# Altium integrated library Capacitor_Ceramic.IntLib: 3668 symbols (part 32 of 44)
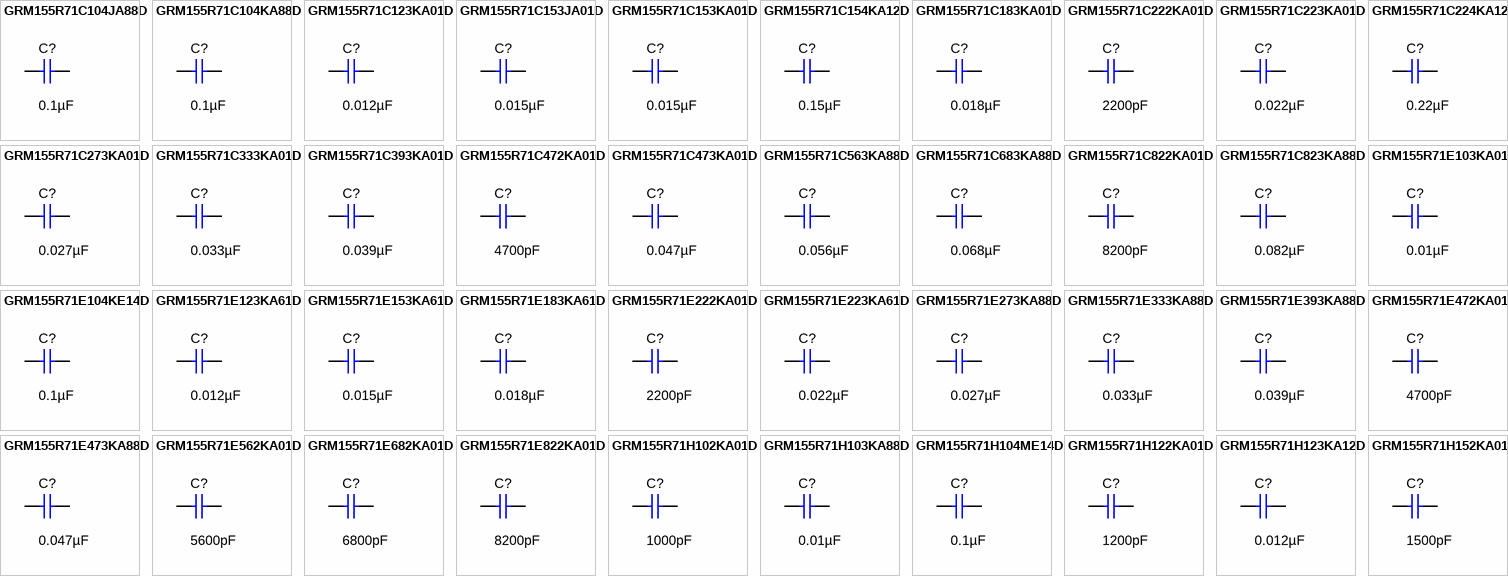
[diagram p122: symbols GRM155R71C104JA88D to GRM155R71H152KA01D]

## GRM155R71H123KA12D
designator C?  ValueDisplayed: 0.012µF  (hidden comment: GRM155R71H123KA12D)
CAP, CERM, 0.012 µF, 50 V,+/- 10%, X7R, 0402; Manufacturer: MuRata; Polarized: N; CompType: Capacitor; Value: 0.012uF; U/M: EA; Cap_F: 0.000000012; Tolerance_%: 10; VDC_V: 50; Value2: 50V; TaMin_C: -55; TaMax_C: 125; Cap_Case: 0402; SizeArea_mm2: 0.5; SizeAreaWB_mm2: 3; SizeX_mm: 1; SizeZ_mm: 0.6; AEC Category: Q200
signal-integrity model Cap
simulation model Cap
footprint 0402
footprint 0402M
footprint 0402L
footprint 0402S
pins: 1, 2

## GRM155R71H152KA01D
designator C?  ValueDisplayed: 1500pF  (hidden comment: GRM155R71H152KA01D)
CAP, CERM, 1500 pF, 50 V,+/- 10%, X7R, 0402; Manufacturer: MuRata; Polarized: N; CompType: Capacitor; Value: 1500pF; U/M: EA; Cap_F: 0.0000000015; Tolerance_%: 10; VDC_V: 50; Value2: 50V; TaMin_C: -55; TaMax_C: 125; Cap_Case: 0402; SizeArea_mm2: 0.5; SizeAreaWB_mm2: 3; SizeX_mm: 1; SizeZ_mm: 0.6; AEC Category: Q200
signal-integrity model Cap
simulation model Cap
footprint 0402
footprint 0402M
footprint 0402L
footprint 0402S
pins: 1, 2

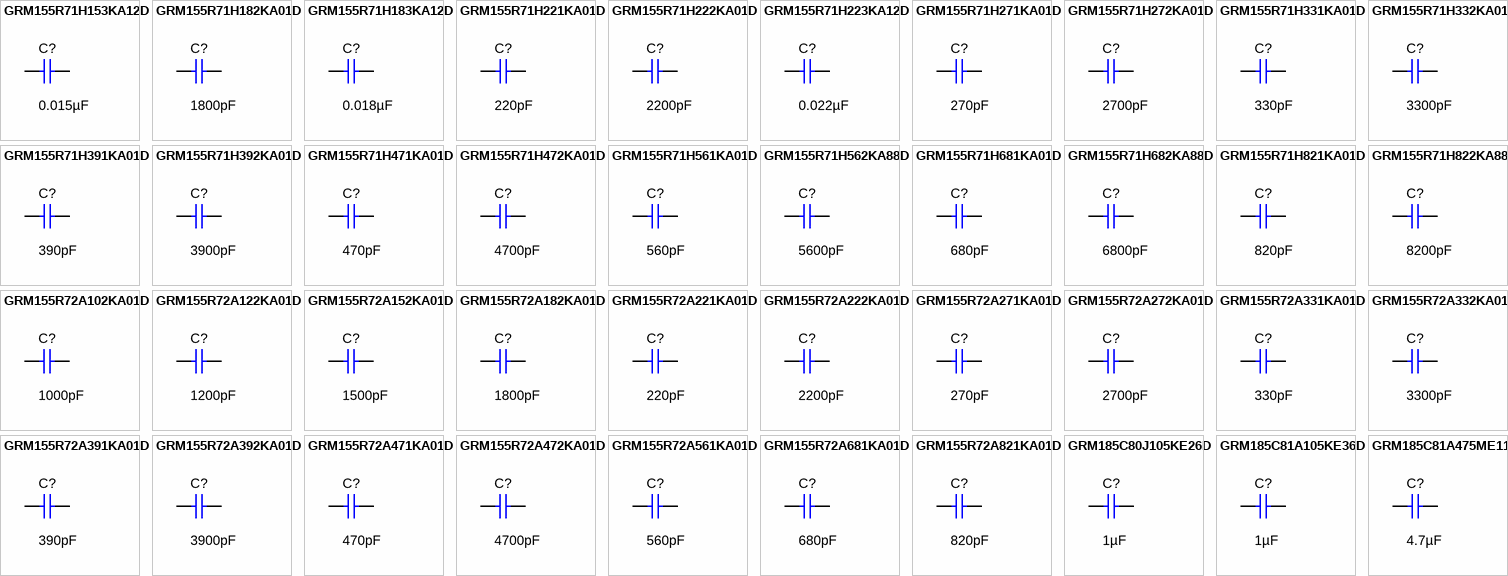
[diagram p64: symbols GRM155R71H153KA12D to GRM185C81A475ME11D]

## GRM155R71H153KA12D
designator C?  ValueDisplayed: 0.015µF  (hidden comment: GRM155R71H153KA12D)
CAP, CERM, 0.015 µF, 50 V,+/- 10%, X7R, 0402; Manufacturer: MuRata; Polarized: N; CompType: Capacitor; Value: 0.015uF; U/M: EA; Cap_F: 0.000000015; Tolerance_%: 10; VDC_V: 50; Value2: 50V; TaMin_C: -55; TaMax_C: 125; Cap_Case: 0402; SizeArea_mm2: 0.5; SizeAreaWB_mm2: 3; SizeX_mm: 1; SizeZ_mm: 0.6; AEC Category: Q200; Green_Lifecycle: Active; Green_REACh: Passed
signal-integrity model Cap
simulation model Cap
footprint 0402
footprint 0402M
footprint 0402L
footprint 0402S
pins: 1, 2

## GRM155R71H182KA01D
designator C?  ValueDisplayed: 1800pF  (hidden comment: GRM155R71H182KA01D)
CAP, CERM, 1800 pF, 50 V,+/- 10%, X7R, 0402; Manufacturer: MuRata; Polarized: N; CompType: Capacitor; Value: 1800pF; U/M: EA; Cap_F: 0.0000000018; Tolerance_%: 10; VDC_V: 50; Value2: 50V; TaMin_C: -55; TaMax_C: 125; Cap_Case: 0402; SizeArea_mm2: 0.5; SizeAreaWB_mm2: 3; SizeX_mm: 1; SizeZ_mm: 0.6; AEC Category: Q200; Green_Lifecycle: Active; Green_REACh: Passed
signal-integrity model Cap
simulation model Cap
footprint 0402
footprint 0402M
footprint 0402L
footprint 0402S
pins: 1, 2

## GRM155R71H183KA12D
designator C?  ValueDisplayed: 0.018µF  (hidden comment: GRM155R71H183KA12D)
CAP, CERM, 0.018 µF, 50 V,+/- 10%, X7R, 0402; Manufacturer: MuRata; Polarized: N; CompType: Capacitor; Value: 0.018uF; U/M: EA; Cap_F: 0.000000018; Tolerance_%: 10; VDC_V: 50; Value2: 50V; TaMin_C: -55; TaMax_C: 125; Cap_Case: 0402; SizeArea_mm2: 0.5; SizeAreaWB_mm2: 3; SizeX_mm: 1; SizeZ_mm: 0.6; AEC Category: Q200
signal-integrity model Cap
simulation model Cap
footprint 0402
footprint 0402M
footprint 0402L
footprint 0402S
pins: 1, 2

## GRM155R71H221KA01D
designator C?  ValueDisplayed: 220pF  (hidden comment: GRM155R71H221KA01D)
CAP, CERM, 220 pF, 50 V,+/- 10%, X7R, 0402; Manufacturer: MuRata; Polarized: N; CompType: Capacitor; Value: 220pF; U/M: EA; Cap_F: 0.00000000022; Tolerance_%: 10; VDC_V: 50; Value2: 50V; TaMin_C: -55; TaMax_C: 125; Cap_Case: 0402; SizeArea_mm2: 0.5; SizeAreaWB_mm2: 3; SizeX_mm: 1; SizeZ_mm: 0.6; AEC Category: Q200
signal-integrity model Cap
simulation model Cap
footprint 0402
footprint 0402M
footprint 0402L
footprint 0402S
pins: 1, 2

## GRM155R71H222KA01D
designator C?  ValueDisplayed: 2200pF  (hidden comment: GRM155R71H222KA01D)
CAP, CERM, 2200 pF, 50 V,+/- 10%, X7R, 0402; Manufacturer: MuRata; Polarized: N; CompType: Capacitor; Value: 2200pF; U/M: EA; Cap_F: 0.0000000022; Tolerance_%: 10; VDC_V: 50; Value2: 50V; TaMin_C: -55; TaMax_C: 125; Cap_Case: 0402; SizeArea_mm2: 0.5; SizeAreaWB_mm2: 3; SizeX_mm: 1; SizeZ_mm: 0.6; AEC Category: Q200; Green_Lifecycle: Active; Green_REACh: Passed
signal-integrity model Cap
simulation model Cap
footprint 0402
footprint 0402M
footprint 0402L
footprint 0402S
pins: 1, 2

## GRM155R71H223KA12D
designator C?  ValueDisplayed: 0.022µF  (hidden comment: GRM155R71H223KA12D)
CAP, CERM, 0.022 µF, 50 V,+/- 10%, X7R, 0402; Manufacturer: MuRata; Polarized: N; CompType: Capacitor; Value: 0.022uF; U/M: EA; Cap_F: 0.000000022; Tolerance_%: 10; VDC_V: 50; Value2: 50V; TaMin_C: -55; TaMax_C: 125; Cap_Case: 0402; SizeArea_mm2: 0.5; SizeAreaWB_mm2: 3; SizeX_mm: 1; SizeZ_mm: 0.6; AEC Category: Q200; Green_Lifecycle: Active; Green_REACh: Passed
signal-integrity model Cap
simulation model Cap
footprint 0402
footprint 0402M
footprint 0402L
footprint 0402S
pins: 1, 2

## GRM155R71H271KA01D
designator C?  ValueDisplayed: 270pF  (hidden comment: GRM155R71H271KA01D)
CAP, CERM, 270 pF, 50 V,+/- 10%, X7R, 0402; Manufacturer: MuRata; Polarized: N; CompType: Capacitor; Value: 270pF; U/M: EA; Cap_F: 0.00000000027; Tolerance_%: 10; VDC_V: 50; Value2: 50V; TaMin_C: -55; TaMax_C: 125; Cap_Case: 0402; SizeArea_mm2: 0.5; SizeAreaWB_mm2: 3; SizeX_mm: 1; SizeZ_mm: 0.6; AEC Category: Q200
signal-integrity model Cap
simulation model Cap
footprint 0402
footprint 0402M
footprint 0402L
footprint 0402S
pins: 1, 2

## GRM155R71H272KA01D
designator C?  ValueDisplayed: 2700pF  (hidden comment: GRM155R71H272KA01D)
CAP, CERM, 2700 pF, 50 V,+/- 10%, X7R, 0402; Manufacturer: MuRata; Polarized: N; CompType: Capacitor; Value: 2700pF; U/M: EA; Cap_F: 0.0000000027; Tolerance_%: 10; VDC_V: 50; Value2: 50V; TaMin_C: -55; TaMax_C: 125; Cap_Case: 0402; SizeArea_mm2: 0.5; SizeAreaWB_mm2: 3; SizeX_mm: 1; SizeZ_mm: 0.6; AEC Category: Q200
signal-integrity model Cap
simulation model Cap
footprint 0402
footprint 0402M
footprint 0402L
footprint 0402S
pins: 1, 2

## GRM155R71H331KA01D
designator C?  ValueDisplayed: 330pF  (hidden comment: GRM155R71H331KA01D)
CAP, CERM, 330 pF, 50 V,+/- 10%, X7R, 0402; Manufacturer: MuRata; Polarized: N; CompType: Capacitor; Value: 330pF; U/M: EA; Cap_F: 0.00000000033; Tolerance_%: 10; VDC_V: 50; Value2: 50V; TaMin_C: -55; TaMax_C: 125; Cap_Case: 0402; SizeArea_mm2: 0.5; SizeAreaWB_mm2: 3; SizeX_mm: 1; SizeZ_mm: 0.6; AEC Category: Q200; Green_Lifecycle: Active; Green_REACh: Passed
signal-integrity model Cap
simulation model Cap
footprint 0402
footprint 0402M
footprint 0402L
footprint 0402S
pins: 1, 2

## GRM155R71H332KA01D
designator C?  ValueDisplayed: 3300pF  (hidden comment: GRM155R71H332KA01D)
CAP, CERM, 3300 pF, 50 V,+/- 10%, X7R, 0402; Manufacturer: MuRata; Polarized: N; CompType: Capacitor; Value: 3300pF; U/M: EA; Cap_F: 0.0000000033; Tolerance_%: 10; VDC_V: 50; Value2: 50V; TaMin_C: -55; TaMax_C: 125; Cap_Case: 0402; SizeArea_mm2: 0.5; SizeAreaWB_mm2: 3; SizeX_mm: 1; SizeZ_mm: 0.6; AEC Category: Q200; Green_Lifecycle: Active; Green_REACh: Passed
signal-integrity model Cap
simulation model Cap
footprint 0402
footprint 0402M
footprint 0402L
footprint 0402S
pins: 1, 2

## GRM155R71H391KA01D
designator C?  ValueDisplayed: 390pF  (hidden comment: GRM155R71H391KA01D)
CAP, CERM, 390 pF, 50 V,+/- 10%, X7R, 0402; Manufacturer: MuRata; Polarized: N; CompType: Capacitor; Value: 390pF; U/M: EA; Cap_F: 0.00000000039; Tolerance_%: 10; VDC_V: 50; Value2: 50V; TaMin_C: -55; TaMax_C: 125; Cap_Case: 0402; SizeArea_mm2: 0.5; SizeAreaWB_mm2: 3; SizeX_mm: 1; SizeZ_mm: 0.6; AEC Category: Q200
signal-integrity model Cap
simulation model Cap
footprint 0402
footprint 0402M
footprint 0402L
footprint 0402S
pins: 1, 2

## GRM155R71H392KA01D
designator C?  ValueDisplayed: 3900pF  (hidden comment: GRM155R71H392KA01D)
CAP, CERM, 3900 pF, 50 V,+/- 10%, X7R, 0402; Manufacturer: MuRata; Polarized: N; CompType: Capacitor; Value: 3900pF; U/M: EA; Cap_F: 0.0000000039; Tolerance_%: 10; VDC_V: 50; Value2: 50V; TaMin_C: -55; TaMax_C: 125; Cap_Case: 0402; SizeArea_mm2: 0.5; SizeAreaWB_mm2: 3; SizeX_mm: 1; SizeZ_mm: 0.6; AEC Category: Q200; Green_Lifecycle: Active; Green_REACh: Passed
signal-integrity model Cap
simulation model Cap
footprint 0402
footprint 0402M
footprint 0402L
footprint 0402S
pins: 1, 2

## GRM155R71H471KA01D
designator C?  ValueDisplayed: 470pF  (hidden comment: GRM155R71H471KA01D)
CAP, CERM, 470 pF, 50 V,+/- 10%, X7R, 0402; Manufacturer: MuRata; Polarized: N; CompType: Capacitor; Value: 470pF; U/M: EA; Cap_F: 0.00000000047; Tolerance_%: 10; VDC_V: 50; Value2: 50V; TaMin_C: -55; TaMax_C: 125; Cap_Case: 0402; SizeArea_mm2: 0.5; SizeAreaWB_mm2: 3; SizeX_mm: 1; SizeZ_mm: 0.6; AEC Category: Q200; Green_Lifecycle: Active; Green_REACh: Passed
signal-integrity model Cap
simulation model Cap
footprint 0402
footprint 0402M
footprint 0402L
footprint 0402S
pins: 1, 2

## GRM155R71H472KA01D
designator C?  ValueDisplayed: 4700pF  (hidden comment: GRM155R71H472KA01D)
CAP, CERM, 4700 pF, 50 V,+/- 10%, X7R, 0402; Manufacturer: MuRata; Polarized: N; CompType: Capacitor; Value: 4700pF; U/M: EA; Cap_F: 0.0000000047; Tolerance_%: 10; VDC_V: 50; Value2: 50V; TaMin_C: -55; TaMax_C: 125; Cap_Case: 0402; SizeArea_mm2: 0.5; SizeAreaWB_mm2: 3; SizeX_mm: 1; SizeZ_mm: 0.6; AEC Category: Q200
signal-integrity model Cap
simulation model Cap
footprint 0402
footprint 0402M
footprint 0402L
footprint 0402S
pins: 1, 2

## GRM155R71H561KA01D
designator C?  ValueDisplayed: 560pF  (hidden comment: GRM155R71H561KA01D)
CAP, CERM, 560 pF, 50 V,+/- 10%, X7R, 0402; Manufacturer: MuRata; Polarized: N; CompType: Capacitor; Value: 560pF; U/M: EA; Cap_F: 0.00000000056; Tolerance_%: 10; VDC_V: 50; Value2: 50V; TaMin_C: -55; TaMax_C: 125; Cap_Case: 0402; SizeArea_mm2: 0.5; SizeAreaWB_mm2: 3; SizeX_mm: 1; SizeZ_mm: 0.6; AEC Category: Q200
signal-integrity model Cap
simulation model Cap
footprint 0402
footprint 0402M
footprint 0402L
footprint 0402S
pins: 1, 2

## GRM155R71H562KA88D
designator C?  ValueDisplayed: 5600pF  (hidden comment: GRM155R71H562KA88D)
CAP, CERM, 5600 pF, 50 V,+/- 10%, X7R, 0402; Manufacturer: MuRata; Polarized: N; CompType: Capacitor; Value: 5600pF; U/M: EA; Cap_F: 0.0000000056; Tolerance_%: 10; VDC_V: 50; Value2: 50V; TaMin_C: -55; TaMax_C: 125; Cap_Case: 0402; SizeArea_mm2: 0.5; SizeAreaWB_mm2: 3; SizeX_mm: 1; SizeZ_mm: 0.6; AEC Category: Q200; Green_Lifecycle: Active; Green_REACh: Passed
signal-integrity model Cap
simulation model Cap
footprint 0402
footprint 0402M
footprint 0402L
footprint 0402S
pins: 1, 2

## GRM155R71H681KA01D
designator C?  ValueDisplayed: 680pF  (hidden comment: GRM155R71H681KA01D)
CAP, CERM, 680 pF, 50 V,+/- 10%, X7R, 0402; Manufacturer: MuRata; Polarized: N; CompType: Capacitor; Value: 680pF; U/M: EA; Cap_F: 0.00000000068; Tolerance_%: 10; VDC_V: 50; Value2: 50V; TaMin_C: -55; TaMax_C: 125; Cap_Case: 0402; SizeArea_mm2: 0.5; SizeAreaWB_mm2: 3; SizeX_mm: 1; SizeZ_mm: 0.6; AEC Category: Q200
signal-integrity model Cap
simulation model Cap
footprint 0402
footprint 0402M
footprint 0402L
footprint 0402S
pins: 1, 2

## GRM155R71H682KA88D
designator C?  ValueDisplayed: 6800pF  (hidden comment: GRM155R71H682KA88D)
CAP, CERM, 6800 pF, 50 V,+/- 10%, X7R, 0402; Manufacturer: MuRata; Polarized: N; CompType: Capacitor; Value: 6800pF; U/M: EA; Cap_F: 0.0000000068; Tolerance_%: 10; VDC_V: 50; Value2: 50V; TaMin_C: -55; TaMax_C: 125; Cap_Case: 0402; SizeArea_mm2: 0.5; SizeAreaWB_mm2: 3; SizeX_mm: 1; SizeZ_mm: 0.6; AEC Category: Q200; Green_Lifecycle: Active; Green_REACh: Passed
signal-integrity model Cap
simulation model Cap
footprint 0402
footprint 0402M
footprint 0402L
footprint 0402S
pins: 1, 2

## GRM155R71H821KA01D
designator C?  ValueDisplayed: 820pF  (hidden comment: GRM155R71H821KA01D)
CAP, CERM, 820 pF, 50 V,+/- 10%, X7R, 0402; Manufacturer: MuRata; Polarized: N; CompType: Capacitor; Value: 820pF; U/M: EA; Cap_F: 0.00000000082; Tolerance_%: 10; VDC_V: 50; Value2: 50V; TaMin_C: -55; TaMax_C: 125; Cap_Case: 0402; SizeArea_mm2: 0.5; SizeAreaWB_mm2: 3; SizeX_mm: 1; SizeZ_mm: 0.6; AEC Category: Q200
signal-integrity model Cap
simulation model Cap
footprint 0402
footprint 0402M
footprint 0402L
footprint 0402S
pins: 1, 2

## GRM155R71H822KA88D
designator C?  ValueDisplayed: 8200pF  (hidden comment: GRM155R71H822KA88D)
CAP, CERM, 8200 pF, 50 V,+/- 10%, X7R, 0402; Manufacturer: MuRata; Polarized: N; CompType: Capacitor; Value: 8200pF; U/M: EA; Cap_F: 0.0000000082; Tolerance_%: 10; VDC_V: 50; Value2: 50V; TaMin_C: -55; TaMax_C: 125; Cap_Case: 0402; SizeArea_mm2: 0.5; SizeAreaWB_mm2: 3; SizeX_mm: 1; SizeZ_mm: 0.6; AEC Category: Q200
signal-integrity model Cap
simulation model Cap
footprint 0402
footprint 0402M
footprint 0402L
footprint 0402S
pins: 1, 2

## GRM155R72A102KA01D
designator C?  ValueDisplayed: 1000pF  (hidden comment: GRM155R72A102KA01D)
CAP, CERM, 1000 pF, 100 V,+/- 10%, X7R, 0402; Manufacturer: MuRata; Polarized: N; CompType: Capacitor; Value: 1000pF; U/M: EA; Cap_F: 0.000000001; Tolerance_%: 10; VDC_V: 100; Value2: 100V; TaMin_C: -55; TaMax_C: 125; Cap_Case: 0402; SizeArea_mm2: 0.5; SizeAreaWB_mm2: 3; SizeX_mm: 1; SizeZ_mm: 0.6; AEC Category: Q200
signal-integrity model Cap
simulation model Cap
footprint 0402
footprint 0402M
footprint 0402L
footprint 0402S
pins: 1, 2

## GRM155R72A122KA01D
designator C?  ValueDisplayed: 1200pF  (hidden comment: GRM155R72A122KA01D)
CAP, CERM, 1200 pF, 100 V,+/- 10%, X7R, 0402; Manufacturer: MuRata; Polarized: N; CompType: Capacitor; Value: 1200pF; U/M: EA; Cap_F: 0.0000000012; Tolerance_%: 10; VDC_V: 100; Value2: 100V; TaMin_C: -55; TaMax_C: 125; Cap_Case: 0402; SizeArea_mm2: 0.5; SizeAreaWB_mm2: 3; SizeX_mm: 1; SizeZ_mm: 0.6; AEC Category: Q200
signal-integrity model Cap
simulation model Cap
footprint 0402
footprint 0402M
footprint 0402L
footprint 0402S
pins: 1, 2

## GRM155R72A152KA01D
designator C?  ValueDisplayed: 1500pF  (hidden comment: GRM155R72A152KA01D)
CAP, CERM, 1500 pF, 100 V,+/- 10%, X7R, 0402; Manufacturer: MuRata; Polarized: N; CompType: Capacitor; Value: 1500pF; U/M: EA; Cap_F: 0.0000000015; Tolerance_%: 10; VDC_V: 100; Value2: 100V; TaMin_C: -55; TaMax_C: 125; Cap_Case: 0402; SizeArea_mm2: 0.5; SizeAreaWB_mm2: 3; SizeX_mm: 1; SizeZ_mm: 0.6; AEC Category: Q200
signal-integrity model Cap
simulation model Cap
footprint 0402
footprint 0402M
footprint 0402L
footprint 0402S
pins: 1, 2

## GRM155R72A182KA01D
designator C?  ValueDisplayed: 1800pF  (hidden comment: GRM155R72A182KA01D)
CAP, CERM, 1800 pF, 100 V,+/- 10%, X7R, 0402; Manufacturer: MuRata; Polarized: N; CompType: Capacitor; Value: 1800pF; U/M: EA; Cap_F: 0.0000000018; Tolerance_%: 10; VDC_V: 100; Value2: 100V; TaMin_C: -55; TaMax_C: 125; Cap_Case: 0402; SizeArea_mm2: 0.5; SizeAreaWB_mm2: 3; SizeX_mm: 1; SizeZ_mm: 0.6; AEC Category: Q200
signal-integrity model Cap
simulation model Cap
footprint 0402
footprint 0402M
footprint 0402L
footprint 0402S
pins: 1, 2

## GRM155R72A221KA01D
designator C?  ValueDisplayed: 220pF  (hidden comment: GRM155R72A221KA01D)
CAP, CERM, 220 pF, 100 V,+/- 10%, X7R, 0402; Manufacturer: MuRata; Polarized: N; CompType: Capacitor; Value: 220pF; U/M: EA; Cap_F: 0.00000000022; Tolerance_%: 10; VDC_V: 100; Value2: 100V; TaMin_C: -55; TaMax_C: 125; Cap_Case: 0402; SizeArea_mm2: 0.5; SizeAreaWB_mm2: 3; SizeX_mm: 1; SizeZ_mm: 0.6; AEC Category: Q200
signal-integrity model Cap
simulation model Cap
footprint 0402
footprint 0402M
footprint 0402L
footprint 0402S
pins: 1, 2

## GRM155R72A222KA01D
designator C?  ValueDisplayed: 2200pF  (hidden comment: GRM155R72A222KA01D)
CAP, CERM, 2200 pF, 100 V,+/- 10%, X7R, 0402; Manufacturer: MuRata; Polarized: N; CompType: Capacitor; Value: 2200pF; U/M: EA; Cap_F: 0.0000000022; Tolerance_%: 10; VDC_V: 100; Value2: 100V; TaMin_C: -55; TaMax_C: 125; Cap_Case: 0402; SizeArea_mm2: 0.5; SizeAreaWB_mm2: 3; SizeX_mm: 1; SizeZ_mm: 0.6; AEC Category: Q200
signal-integrity model Cap
simulation model Cap
footprint 0402
footprint 0402M
footprint 0402L
footprint 0402S
pins: 1, 2

## GRM155R72A271KA01D
designator C?  ValueDisplayed: 270pF  (hidden comment: GRM155R72A271KA01D)
CAP, CERM, 270 pF, 100 V,+/- 10%, X7R, 0402; Manufacturer: MuRata; Polarized: N; CompType: Capacitor; Value: 270pF; U/M: EA; Cap_F: 0.00000000027; Tolerance_%: 10; VDC_V: 100; Value2: 100V; TaMin_C: -55; TaMax_C: 125; Cap_Case: 0402; SizeArea_mm2: 0.5; SizeAreaWB_mm2: 3; SizeX_mm: 1; SizeZ_mm: 0.6; AEC Category: Q200
signal-integrity model Cap
simulation model Cap
footprint 0402
footprint 0402M
footprint 0402L
footprint 0402S
pins: 1, 2

## GRM155R72A272KA01D
designator C?  ValueDisplayed: 2700pF  (hidden comment: GRM155R72A272KA01D)
CAP, CERM, 2700 pF, 100 V,+/- 10%, X7R, 0402; Manufacturer: MuRata; Polarized: N; CompType: Capacitor; Value: 2700pF; U/M: EA; Cap_F: 0.0000000027; Tolerance_%: 10; VDC_V: 100; Value2: 100V; TaMin_C: -55; TaMax_C: 125; Cap_Case: 0402; SizeArea_mm2: 0.5; SizeAreaWB_mm2: 3; SizeX_mm: 1; SizeZ_mm: 0.6; AEC Category: Q200; Green_Lifecycle: Active; Green_REACh: Passed
signal-integrity model Cap
simulation model Cap
footprint 0402
footprint 0402M
footprint 0402L
footprint 0402S
pins: 1, 2

## GRM155R72A331KA01D
designator C?  ValueDisplayed: 330pF  (hidden comment: GRM155R72A331KA01D)
CAP, CERM, 330 pF, 100 V,+/- 10%, X7R, 0402; Manufacturer: MuRata; Polarized: N; CompType: Capacitor; Value: 330pF; U/M: EA; Cap_F: 0.00000000033; Tolerance_%: 10; VDC_V: 100; Value2: 100V; TaMin_C: -55; TaMax_C: 125; Cap_Case: 0402; SizeArea_mm2: 0.5; SizeAreaWB_mm2: 3; SizeX_mm: 1; SizeZ_mm: 0.6; AEC Category: Q200
signal-integrity model Cap
simulation model Cap
footprint 0402
footprint 0402M
footprint 0402L
footprint 0402S
pins: 1, 2

## GRM155R72A332KA01D
designator C?  ValueDisplayed: 3300pF  (hidden comment: GRM155R72A332KA01D)
CAP, CERM, 3300 pF, 100 V,+/- 10%, X7R, 0402; Manufacturer: MuRata; Polarized: N; CompType: Capacitor; Value: 3300pF; U/M: EA; Cap_F: 0.0000000033; Tolerance_%: 10; VDC_V: 100; Value2: 100V; TaMin_C: -55; TaMax_C: 125; Cap_Case: 0402; SizeArea_mm2: 0.5; SizeAreaWB_mm2: 3; SizeX_mm: 1; SizeZ_mm: 0.6; AEC Category: Q200; Green_Lifecycle: Active; Green_REACh: Passed
signal-integrity model Cap
simulation model Cap
footprint 0402
footprint 0402M
footprint 0402L
footprint 0402S
pins: 1, 2

## GRM155R72A391KA01D
designator C?  ValueDisplayed: 390pF  (hidden comment: GRM155R72A391KA01D)
CAP, CERM, 390 pF, 100 V,+/- 10%, X7R, 0402; Manufacturer: MuRata; Polarized: N; CompType: Capacitor; Value: 390pF; U/M: EA; Cap_F: 0.00000000039; Tolerance_%: 10; VDC_V: 100; Value2: 100V; TaMin_C: -55; TaMax_C: 125; Cap_Case: 0402; SizeArea_mm2: 0.5; SizeAreaWB_mm2: 3; SizeX_mm: 1; SizeZ_mm: 0.6; AEC Category: Q200
signal-integrity model Cap
simulation model Cap
footprint 0402
footprint 0402M
footprint 0402L
footprint 0402S
pins: 1, 2

## GRM155R72A392KA01D
designator C?  ValueDisplayed: 3900pF  (hidden comment: GRM155R72A392KA01D)
CAP, CERM, 3900 pF, 100 V,+/- 10%, X7R, 0402; Manufacturer: MuRata; Polarized: N; CompType: Capacitor; Value: 3900pF; U/M: EA; Cap_F: 0.0000000039; Tolerance_%: 10; VDC_V: 100; Value2: 100V; TaMin_C: -55; TaMax_C: 125; Cap_Case: 0402; SizeArea_mm2: 0.5; SizeAreaWB_mm2: 3; SizeX_mm: 1; SizeZ_mm: 0.6; AEC Category: Q200
signal-integrity model Cap
simulation model Cap
footprint 0402
footprint 0402M
footprint 0402L
footprint 0402S
pins: 1, 2

## GRM155R72A471KA01D
designator C?  ValueDisplayed: 470pF  (hidden comment: GRM155R72A471KA01D)
CAP, CERM, 470 pF, 100 V,+/- 10%, X7R, 0402; Manufacturer: MuRata; Polarized: N; CompType: Capacitor; Value: 470pF; U/M: EA; Cap_F: 0.00000000047; Tolerance_%: 10; VDC_V: 100; Value2: 100V; TaMin_C: -55; TaMax_C: 125; Cap_Case: 0402; SizeArea_mm2: 0.5; SizeAreaWB_mm2: 3; SizeX_mm: 1; SizeZ_mm: 0.6; AEC Category: Q200
signal-integrity model Cap
simulation model Cap
footprint 0402
footprint 0402M
footprint 0402L
footprint 0402S
pins: 1, 2

## GRM155R72A472KA01D
designator C?  ValueDisplayed: 4700pF  (hidden comment: GRM155R72A472KA01D)
CAP, CERM, 4700 pF, 100 V,+/- 10%, X7R, 0402; Manufacturer: MuRata; Polarized: N; CompType: Capacitor; Value: 4700pF; U/M: EA; Cap_F: 0.0000000047; Tolerance_%: 10; VDC_V: 100; Value2: 100V; TaMin_C: -55; TaMax_C: 125; Cap_Case: 0402; SizeArea_mm2: 0.5; SizeAreaWB_mm2: 3; SizeX_mm: 1; SizeZ_mm: 0.6; AEC Category: Q200
signal-integrity model Cap
simulation model Cap
footprint 0402
footprint 0402M
footprint 0402L
footprint 0402S
pins: 1, 2

## GRM155R72A561KA01D
designator C?  ValueDisplayed: 560pF  (hidden comment: GRM155R72A561KA01D)
CAP, CERM, 560 pF, 100 V,+/- 10%, X7R, 0402; Manufacturer: MuRata; Polarized: N; CompType: Capacitor; Value: 560pF; U/M: EA; Cap_F: 0.00000000056; Tolerance_%: 10; VDC_V: 100; Value2: 100V; TaMin_C: -55; TaMax_C: 125; Cap_Case: 0402; SizeArea_mm2: 0.5; SizeAreaWB_mm2: 3; SizeX_mm: 1; SizeZ_mm: 0.6; AEC Category: Q200
signal-integrity model Cap
simulation model Cap
footprint 0402
footprint 0402M
footprint 0402L
footprint 0402S
pins: 1, 2

## GRM155R72A681KA01D
designator C?  ValueDisplayed: 680pF  (hidden comment: GRM155R72A681KA01D)
CAP, CERM, 680 pF, 100 V,+/- 10%, X7R, 0402; Manufacturer: MuRata; Polarized: N; CompType: Capacitor; Value: 680pF; U/M: EA; Cap_F: 0.00000000068; Tolerance_%: 10; VDC_V: 100; Value2: 100V; TaMin_C: -55; TaMax_C: 125; Cap_Case: 0402; SizeArea_mm2: 0.5; SizeAreaWB_mm2: 3; SizeX_mm: 1; SizeZ_mm: 0.6; AEC Category: Q200
signal-integrity model Cap
simulation model Cap
footprint 0402
footprint 0402M
footprint 0402L
footprint 0402S
pins: 1, 2

## GRM155R72A821KA01D
designator C?  ValueDisplayed: 820pF  (hidden comment: GRM155R72A821KA01D)
CAP, CERM, 820 pF, 100 V,+/- 10%, X7R, 0402; Manufacturer: MuRata; Polarized: N; CompType: Capacitor; Value: 820pF; U/M: EA; Cap_F: 0.00000000082; Tolerance_%: 10; VDC_V: 100; Value2: 100V; TaMin_C: -55; TaMax_C: 125; Cap_Case: 0402; SizeArea_mm2: 0.5; SizeAreaWB_mm2: 3; SizeX_mm: 1; SizeZ_mm: 0.6; AEC Category: Q200
signal-integrity model Cap
simulation model Cap
footprint 0402
footprint 0402M
footprint 0402L
footprint 0402S
pins: 1, 2

## GRM185C80J105KE26D
designator C?  ValueDisplayed: 1µF  (hidden comment: GRM185C80J105KE26D)
CAP, CERM, 1 µF, 6.3 V,+/- 10%, X6S, 0603; Manufacturer: MuRata; Polarized: N; CompType: Capacitor; Value: 1uF; U/M: EA; Cap_F: 0.000001; Tolerance_%: 10; VDC_V: 6.3; Value2: 6.3V; TaMin_C: -55; TaMax_C: 105; Cap_Case: 0603; SizeArea_mm2: 1.28; SizeAreaWB_mm2: 4.68; SizeX_mm: 1.6; SizeY_mm: 0.8; SizeZ_mm: 1; AEC Category: Q200; Green_Lifecycle: Active; Green_REACh: Passed
signal-integrity model Cap
simulation model Cap
footprint 0603
footprint 0603M
footprint 0603L
footprint 0603_HV
footprint 0603S
pins: 1, 2

## GRM185C81A105KE36D
designator C?  ValueDisplayed: 1µF  (hidden comment: GRM185C81A105KE36D)
CAP, CERM, 1 µF, 10 V,+/- 10%, X6S, 0603; Manufacturer: MuRata; Polarized: N; CompType: Capacitor; Value: 1uF; U/M: EA; Cap_F: 0.000001; Tolerance_%: 10; Value2: 10V; TaMin_C: -55; TaMax_C: 105; Cap_Case: 0603; SizeArea_mm2: 1.28; SizeAreaWB_mm2: 4.68; SizeX_mm: 1.6; SizeY_mm: 0.8; SizeZ_mm: 1; AEC Category: Q200
signal-integrity model Cap
simulation model Cap
footprint 0603
footprint 0603M
footprint 0603L
footprint 0603_HV
footprint 0603S
pins: 1, 2

## GRM185C81A475ME11D
designator C?  ValueDisplayed: 4.7µF  (hidden comment: GRM185C81A475ME11D)
CAP, CERM, 4.7 µF, 10 V,+/- 20%, X6S, 0603; Manufacturer: MuRata; Polarized: N; CompType: Capacitor; Value: 4.7uF; U/M: EA; Cap_F: 0.0000047; Tolerance_%: 20; VDC_V: 10; Value2: 10V; TaMin_C: -55; TaMax_C: 105; Cap_Case: 0603; SizeArea_mm2: 1.28; SizeAreaWB_mm2: 4.68; SizeX_mm: 1.6; SizeY_mm: 0.8; SizeZ_mm: 1; AEC Category: Q200
signal-integrity model Cap
simulation model Cap
footprint 0603
footprint 0603M
footprint 0603L
footprint 0603_HV
footprint 0603S
pins: 1, 2

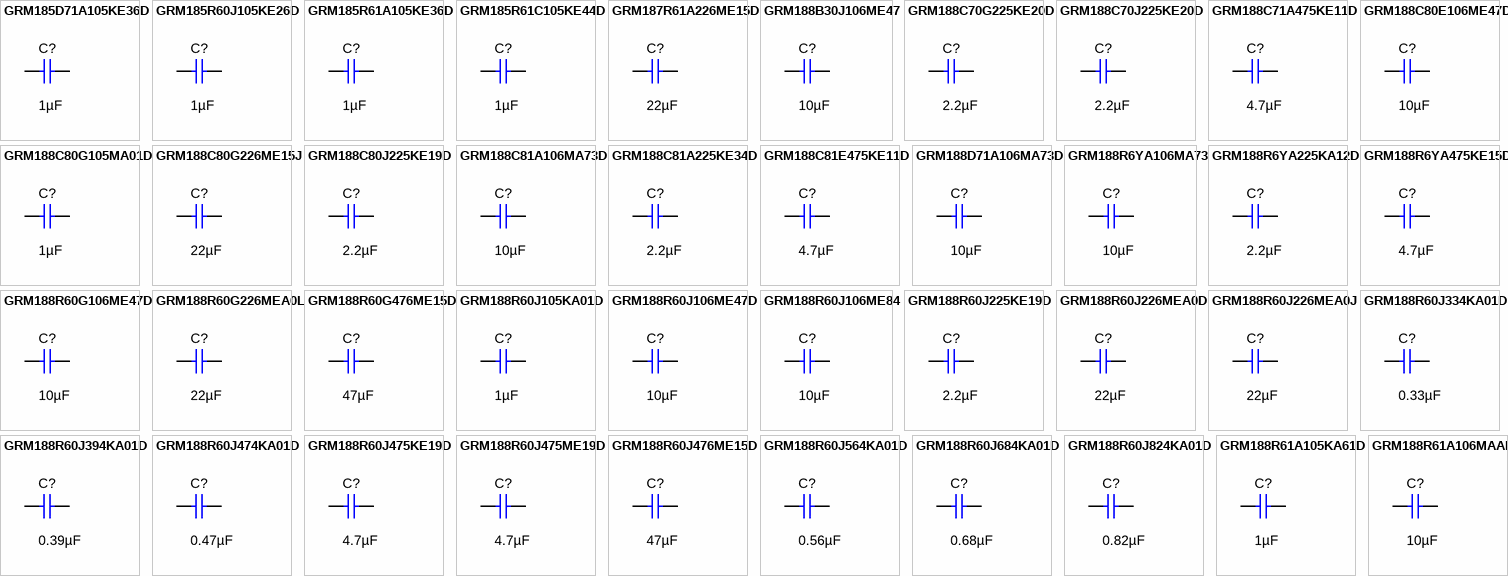
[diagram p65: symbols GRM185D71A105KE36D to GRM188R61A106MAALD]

## GRM185D71A105KE36D
designator C?  ValueDisplayed: 1µF  (hidden comment: GRM185D71A105KE36D)
CAP, CERM, 1 µF, 10 V,+/- 10%, X7T, 0603; Manufacturer: MuRata; Polarized: N; CompType: Capacitor; Value: 1uF; U/M: EA; Cap_F: 0.000001; Tolerance_%: 10; Value2: 10V; TaMin_C: -55; TaMax_C: 125; Cap_Case: 0603; SizeArea_mm2: 1.28; SizeAreaWB_mm2: 4.68; SizeX_mm: 1.6; SizeY_mm: 0.8; SizeZ_mm: 1; AEC Category: Q200; Green_Lifecycle: Active; Green_REACh: Passed
signal-integrity model Cap
simulation model Cap
footprint 0603
footprint 0603M
footprint 0603L
footprint 0603_HV
footprint 0603S
pins: 1, 2

## GRM185R60J105KE26D
designator C?  ValueDisplayed: 1µF  (hidden comment: GRM185R60J105KE26D)
CAP, CERM, 1 µF, 6.3 V,+/- 10%, X5R, 0603; Manufacturer: MuRata; Polarized: N; CompType: Capacitor; Value: 1uF; U/M: EA; Cap_F: 0.000001; Tolerance_%: 10; VDC_V: 6.3; Value2: 6.3V; TaMin_C: -55; TaMax_C: 85; Cap_Case: 0603; SizeArea_mm2: 1.28; SizeAreaWB_mm2: 4.68; SizeX_mm: 1.6; SizeY_mm: 0.8; SizeZ_mm: 1; AEC Category: Q200; Green_Lifecycle: Active; Green_REACh: Passed
signal-integrity model Cap
simulation model Cap
footprint 0603
footprint 0603M
footprint 0603L
footprint 0603_HV
footprint 0603S
pins: 1, 2

## GRM185R61A105KE36D
designator C?  ValueDisplayed: 1µF  (hidden comment: GRM185R61A105KE36D)
CAP, CERM, 1 µF, 10 V,+/- 10%, X5R, 0603; Manufacturer: MuRata; Polarized: N; CompType: Capacitor; Value: 1uF; U/M: EA; Cap_F: 0.000001; Tolerance_%: 10; Value2: 10V; TaMin_C: -55; TaMax_C: 85; Cap_Case: 0603; SizeArea_mm2: 1.28; SizeAreaWB_mm2: 4.68; SizeX_mm: 1.6; SizeY_mm: 0.8; SizeZ_mm: 1; AEC Category: Q200; Green_Lifecycle: Not Set; Green_REACh: Incomplete
signal-integrity model Cap
simulation model Cap
footprint 0603
footprint 0603M
footprint 0603L
footprint 0603_HV
footprint 0603S
pins: 1, 2

## GRM185R61C105KE44D
designator C?  ValueDisplayed: 1µF  (hidden comment: GRM185R61C105KE44D)
CAP, CERM, 1 µF, 16 V,+/- 10%, X5R, 0603; Manufacturer: MuRata; Polarized: N; CompType: Capacitor; Value: 1uF; U/M: EA; Cap_F: 0.000001; Tolerance_%: 10; VDC_V: 16; Value2: 16V; TaMin_C: -55; TaMax_C: 85; Cap_Case: 0603; SizeArea_mm2: 1.28; SizeAreaWB_mm2: 4.68; SizeX_mm: 1.6; SizeY_mm: 0.8; SizeZ_mm: 1; AEC Category: Q200; Green_Lifecycle: Active; Green_REACh: Passed
signal-integrity model Cap
simulation model Cap
footprint 0603
footprint 0603M
footprint 0603L
footprint 0603_HV
footprint 0603S
pins: 1, 2

## GRM187R61A226ME15D
designator C?  ValueDisplayed: 22µF  (hidden comment: GRM187R61A226ME15D)
CAP, CERM, 22 µF, 10 V,+/- 20%, X5R, 0603; Manufacturer: MuRata; Polarized: N; CompType: Capacitor; Value: 22uF; U/M: EA; Cap_F: 0.000022; Tolerance_%: 20; VDC_V: 10; Value2: 10V; TaMin_C: -55; TaMax_C: 85; Cap_Case: 0603; SizeArea_mm2: 1.28; SizeAreaWB_mm2: 4.68; SizeX_mm: 1.6; SizeY_mm: 0.8; SizeZ_mm: 1; AEC Category: Q200
signal-integrity model Cap
simulation model Cap
footprint 0603
footprint 0603M
footprint 0603L
footprint 0603_HV
footprint 0603S
pins: 1, 2

## GRM188B30J106ME47
designator C?  ValueDisplayed: 10µF  (hidden comment: GRM188B30J106ME47)
CAP, CERM, 10 µF, 6.3 V,+/- 10%, B, 0603; Manufacturer: MuRata; Polarized: N; CompType: Capacitor; Value: 10uF; U/M: EA; Cap_F: 0.00001; Tolerance_%: 10; VDC_V: 6.3; Value2: 6.3V; TaMin_C: -25; TaMax_C: 85; Cap_Case: 0603; SizeArea_mm2: 1.28; SizeAreaWB_mm2: 4.68; SizeX_mm: 1.6; SizeY_mm: 0.8; SizeZ_mm: 1; AEC Category: Q200; Green_Lifecycle: Not Set; Green_REACh: Incomplete
signal-integrity model Cap
simulation model Cap
footprint 0603
footprint 0603M
footprint 0603L
footprint 0603_HV
footprint 0603S
pins: 1, 2

## GRM188C70G225KE20D
designator C?  ValueDisplayed: 2.2µF  (hidden comment: GRM188C70G225KE20D)
CAP, CERM, 2.2 µF, 4 V,+/- 10%, X7S, 0603; Manufacturer: MuRata; Polarized: N; CompType: Capacitor; Value: 2.2uF; U/M: EA; Cap_F: 0.0000022; Tolerance_%: 10; VDC_V: 4; Value2: 4V; TaMin_C: -55; TaMax_C: 125; Cap_Case: 0603; SizeArea_mm2: 1.28; SizeAreaWB_mm2: 4.68; SizeX_mm: 1.6; SizeY_mm: 0.8; SizeZ_mm: 1; AEC Category: Q200
signal-integrity model Cap
simulation model Cap
footprint 0603
footprint 0603M
footprint 0603L
footprint 0603_HV
footprint 0603S
pins: 1, 2

## GRM188C70J225KE20D
designator C?  ValueDisplayed: 2.2µF  (hidden comment: GRM188C70J225KE20D)
CAP, CERM, 2.2 µF, 6.3 V,+/- 10%, X7S, 0603; Manufacturer: MuRata; Polarized: N; CompType: Capacitor; Value: 2.2uF; U/M: EA; Cap_F: 0.0000022; Tolerance_%: 10; VDC_V: 6.3; Value2: 6.3V; TaMin_C: -55; TaMax_C: 125; Cap_Case: 0603; SizeArea_mm2: 1.28; SizeAreaWB_mm2: 4.68; SizeX_mm: 1.6; SizeY_mm: 0.8; SizeZ_mm: 1; AEC Category: Q200; Green_Lifecycle: Active; Green_REACh: Passed
signal-integrity model Cap
simulation model Cap
footprint 0603
footprint 0603M
footprint 0603L
footprint 0603_HV
footprint 0603S
pins: 1, 2

## GRM188C71A475KE11D
designator C?  ValueDisplayed: 4.7µF  (hidden comment: GRM188C71A475KE11D)
CAP, CERM, 4.7 µF, 10 V,+/- 10%, X7S, 0603; Manufacturer: MuRata; Polarized: N; CompType: Capacitor; Value: 4.7uF; U/M: EA; Cap_F: 0.0000047; Tolerance_%: 10; Value2: 10V; TaMin_C: -55; TaMax_C: 125; Cap_Case: 0603; SizeArea_mm2: 1.28; SizeAreaWB_mm2: 4.68; SizeX_mm: 1.6; SizeY_mm: 0.8; SizeZ_mm: 1; AEC Category: Q200
signal-integrity model Cap
simulation model Cap
footprint 0603
footprint 0603M
footprint 0603L
footprint 0603_HV
footprint 0603S
pins: 1, 2

## GRM188C80E106ME47D
designator C?  ValueDisplayed: 10µF  (hidden comment: GRM188C80E106ME47D)
CAP, CERM, 10 µF, 2.5 V,+/- 20%, X6S, 0603; Manufacturer: MuRata; Polarized: N; CompType: Capacitor; Value: 10uF; U/M: EA; Cap_F: 0.00001; Tolerance_%: 20; ESR_ohm: 0.003; Value1: 0.003 ohm; VDC_V: 2.5; Value2: 2.5V; IRMS_A: 3.002; TaMin_C: -55; TaMax_C: 105; Cap_Case: 0603; SizeArea_mm2: 1.28; SizeAreaWB_mm2: 4.68; SizeX_mm: 1.6; SizeY_mm: 0.8; SizeZ_mm: 1; AEC Category: Q200
signal-integrity model Cap
simulation model Cap
footprint 0603
footprint 0603M
footprint 0603L
footprint 0603_HV
footprint 0603S
pins: 1, 2

## GRM188C80G105MA01D
designator C?  ValueDisplayed: 1µF  (hidden comment: GRM188C80G105MA01D)
CAP, CERM, 1 µF, 4 V,+/- 20%, X6S, 0603; Manufacturer: MuRata; Polarized: N; CompType: Capacitor; Value: 1uF; U/M: EA; Cap_F: 0.000001; Tolerance_%: 20; VDC_V: 4; Value2: 4V; TaMin_C: -55; TaMax_C: 105; Cap_Case: 0603; SizeArea_mm2: 1.28; SizeAreaWB_mm2: 4.68; SizeX_mm: 1.6; SizeY_mm: 0.8; SizeZ_mm: 1; AEC Category: Q200
signal-integrity model Cap
simulation model Cap
footprint 0603
footprint 0603M
footprint 0603L
footprint 0603_HV
footprint 0603S
pins: 1, 2

## GRM188C80G226ME15J
designator C?  ValueDisplayed: 22µF  (hidden comment: GRM188C80G226ME15J)
CAP, CERM, 22 µF, 4 V,+/- 20%, X6S, 0603; Manufacturer: MuRata; Polarized: N; CompType: Capacitor; Value: 22uF; U/M: EA; Cap_F: 0.000022; Tolerance_%: 20; VDC_V: 4; Value2: 4V; TaMin_C: -55; TaMax_C: 105; Cap_Case: 0603; SizeArea_mm2: 1.28; SizeAreaWB_mm2: 4.68; SizeX_mm: 1.6; SizeY_mm: 0.8; SizeZ_mm: 1; AEC Category: Q200
signal-integrity model Cap
simulation model Cap
footprint 0603
footprint 0603M
footprint 0603L
footprint 0603_HV
footprint 0603S
pins: 1, 2

## GRM188C80J225KE19D
designator C?  ValueDisplayed: 2.2µF  (hidden comment: GRM188C80J225KE19D)
CAP, CERM, 2.2 µF, 6.3 V,+/- 10%, X6S, 0603; Manufacturer: MuRata; Polarized: N; CompType: Capacitor; Value: 2.2uF; U/M: EA; Cap_F: 0.0000022; Tolerance_%: 10; VDC_V: 6.3; Value2: 6.3V; TaMin_C: -55; TaMax_C: 105; Cap_Case: 0603; SizeArea_mm2: 1.28; SizeAreaWB_mm2: 4.68; SizeX_mm: 1.6; SizeY_mm: 0.8; SizeZ_mm: 1; AEC Category: Q200
signal-integrity model Cap
simulation model Cap
footprint 0603
footprint 0603M
footprint 0603L
footprint 0603_HV
footprint 0603S
pins: 1, 2

## GRM188C81A106MA73D
designator C?  ValueDisplayed: 10µF  (hidden comment: GRM188C81A106MA73D)
CAP, CERM, 10 µF, 10 V,+/- 20%, X6S, 0603; Manufacturer: MuRata; Polarized: N; CompType: Capacitor; Value: 10uF; U/M: EA; Cap_F: 0.00001; Tolerance_%: 20; VDC_V: 10; Value2: 10V; TaMin_C: -55; TaMax_C: 105; Cap_Case: 0603; SizeArea_mm2: 1.28; SizeAreaWB_mm2: 4.68; SizeX_mm: 1.6; SizeY_mm: 0.8; SizeZ_mm: 1; AEC Category: Q200; Green_Lifecycle: Active; Green_REACh: Passed
signal-integrity model Cap
simulation model Cap
footprint 0603
footprint 0603M
footprint 0603L
footprint 0603_HV
footprint 0603S
pins: 1, 2

## GRM188C81A225KE34D
designator C?  ValueDisplayed: 2.2µF  (hidden comment: GRM188C81A225KE34D)
CAP, CERM, 2.2 µF, 10 V,+/- 10%, X6S, 0603; Manufacturer: MuRata; Polarized: N; CompType: Capacitor; Value: 2.2uF; U/M: EA; Cap_F: 0.0000022; Tolerance_%: 10; Value2: 10V; TaMin_C: -55; TaMax_C: 105; Cap_Case: 0603; SizeArea_mm2: 1.28; SizeAreaWB_mm2: 4.68; SizeX_mm: 1.6; SizeY_mm: 0.8; SizeZ_mm: 1; AEC Category: Q200; Green_Lifecycle: Active; Green_REACh: Passed
signal-integrity model Cap
simulation model Cap
footprint 0603
footprint 0603M
footprint 0603L
footprint 0603_HV
footprint 0603S
pins: 1, 2

## GRM188C81E475KE11D
designator C?  ValueDisplayed: 4.7µF  (hidden comment: GRM188C81E475KE11D)
CAP, CERM, 4.7 µF, 25 V,+/- 10%, X6S, 0603; Manufacturer: MuRata; Polarized: N; CompType: Capacitor; Value: 4.7uF; U/M: EA; Cap_F: 0.0000047; Tolerance_%: 10; VDC_V: 25; Value2: 25V; TaMin_C: -55; TaMax_C: 105; Cap_Case: 0603; SizeArea_mm2: 1.28; SizeAreaWB_mm2: 4.68; SizeX_mm: 1.6; SizeY_mm: 0.8; SizeZ_mm: 1; AEC Category: Q200
signal-integrity model Cap
simulation model Cap
footprint 0603
footprint 0603M
footprint 0603L
footprint 0603_HV
footprint 0603S
pins: 1, 2

## GRM188D71A106MA73D
designator C?  ValueDisplayed: 10µF  (hidden comment: GRM188D71A106MA73D)
CAP, CERM, 10 µF, 10 V,+/- 20%, X7T, 0603; Manufacturer: MuRata; Polarized: N; CompType: Capacitor; Value: 10uF; U/M: EA; Cap_F: 0.00001; Tolerance_%: 20; VDC_V: 10; Value2: 10V; TaMin_C: -55; TaMax_C: 125; Cap_Case: 0603; SizeArea_mm2: 1.28; SizeAreaWB_mm2: 4.68; SizeX_mm: 1.6; SizeY_mm: 0.8; SizeZ_mm: 1; AEC Category: Q200
signal-integrity model Cap
simulation model Cap
footprint 0603
footprint 0603M
footprint 0603L
footprint 0603_HV
footprint 0603S
pins: 1, 2

## GRM188R6YA106MA73
designator C?  ValueDisplayed: 10µF  (hidden comment: GRM188R6YA106MA73)
CAP, CERM, 10 µF, 35 V,+/- 20%, X5R, 0603; Manufacturer: Nichicon; Polarized: N; CompType: Capacitor; Value: 10uF; U/M: EA; Cap_F: 0.00001; Tolerance_%: 20; VDC_V: 35; Value2: 35V; TaMin_C: -55; TaMax_C: 85; Cap_Case: 0603; SizeArea_mm2: 1.28; SizeAreaWB_mm2: 4.68; SizeX_mm: 1.6; SizeY_mm: 0.8; SizeZ_mm: 1; AEC Category: Q200
signal-integrity model Cap
simulation model Cap
footprint 0603
footprint 0603M
footprint 0603L
footprint 0603_HV
footprint 0603S
pins: 1, 2

## GRM188R6YA225KA12D
designator C?  ValueDisplayed: 2.2µF  (hidden comment: GRM188R6YA225KA12D)
CAP, CERM, 2.2 µF, 35 V,+/- 10%, X5R, 0603; Manufacturer: MuRata; Polarized: N; CompType: Capacitor; Value: 2.2uF; U/M: EA; Cap_F: 0.0000022; Tolerance_%: 10; VDC_V: 35; Value2: 35V; TaMin_C: -55; TaMax_C: 85; Cap_Case: 0603; SizeArea_mm2: 1.28; SizeAreaWB_mm2: 4.68; SizeX_mm: 1.6; SizeY_mm: 0.8; SizeZ_mm: 1; AEC Category: Q200; Green_Lifecycle: Active; Green_REACh: Passed
signal-integrity model Cap
simulation model Cap
footprint 0603
footprint 0603M
footprint 0603L
footprint 0603_HV
footprint 0603S
pins: 1, 2

## GRM188R6YA475KE15D
designator C?  ValueDisplayed: 4.7µF  (hidden comment: GRM188R6YA475KE15D)
CAP, CERM, 4.7 µF, 35 V,+/- 10%, X5R, 0603; Manufacturer: MuRata; Polarized: N; CompType: Capacitor; Value: 4.7uF; U/M: EA; Cap_F: 0.0000047; Tolerance_%: 10; VDC_V: 35; Value2: 35V; TaMin_C: -55; TaMax_C: 85; Cap_Case: 0603; SizeArea_mm2: 1.28; SizeAreaWB_mm2: 4.68; SizeX_mm: 1.6; SizeY_mm: 0.8; SizeZ_mm: 1; AEC Category: Q200; Green_Lifecycle: Active; Green_REACh: Passed
signal-integrity model Cap
simulation model Cap
footprint 0603
footprint 0603M
footprint 0603L
footprint 0603_HV
footprint 0603S
pins: 1, 2

## GRM188R60G106ME47D
designator C?  ValueDisplayed: 10µF  (hidden comment: GRM188R60G106ME47D)
CAP, CERM, 10 µF, 4 V,+/- 20%, X5R, 0603; Manufacturer: MuRata; Polarized: N; CompType: Capacitor; Value: 10uF; U/M: EA; Cap_F: 0.00001; Tolerance_%: 20; ESR_ohm: 0.003; Value1: 0.003 ohm; VDC_V: 4; Value2: 4V; IRMS_A: 3; TaMin_C: -55; TaMax_C: 85; Cap_Case: 0603; SizeArea_mm2: 1.28; SizeAreaWB_mm2: 4.68; SizeX_mm: 1.6; SizeY_mm: 0.8; SizeZ_mm: 1; AEC Category: Q200
signal-integrity model Cap
simulation model Cap
footprint 0603
footprint 0603M
footprint 0603L
footprint 0603_HV
footprint 0603S
pins: 1, 2

## GRM188R60G226MEA0L
designator C?  ValueDisplayed: 22µF  (hidden comment: GRM188R60G226MEA0L)
CAP, CERM, 22 µF, 4 V,+/- 20%, X5R, 0603; Manufacturer: MuRata; Polarized: N; CompType: Capacitor; Value: 22uF; U/M: EA; Cap_F: 0.000022; Tolerance_%: 20; ESR_ohm: 0.01; Value1: 0.01 ohm; VDC_V: 4; Value2: 4V; IRMS_A: 1.65; TaMin_C: -55; TaMax_C: 85; Cap_Case: 0603; SizeArea_mm2: 1.28; SizeAreaWB_mm2: 4.68; SizeX_mm: 1.6; SizeY_mm: 0.8; SizeZ_mm: 1; AEC Category: Q200; Green_Lifecycle: Active; Green_REACh: Passed
signal-integrity model Cap
simulation model Cap
footprint 0603
footprint 0603M
footprint 0603L
footprint 0603_HV
footprint 0603S
pins: 1, 2

## GRM188R60G476ME15D
designator C?  ValueDisplayed: 47µF  (hidden comment: GRM188R60G476ME15D)
CAP, CERM, 47 µF, 4 V,+/- 10%, X5R, 0603; Manufacturer: MuRata; Polarized: N; CompType: Capacitor; Value: 47uF; U/M: EA; Cap_F: 0.000047; Tolerance_%: 10; VDC_V: 4; Value2: 4V; TaMin_C: -55; TaMax_C: 85; Cap_Case: 0603; SizeArea_mm2: 1.28; SizeAreaWB_mm2: 4.68; SizeX_mm: 1.6; SizeY_mm: 0.8; SizeZ_mm: 1; AEC Category: Q200
signal-integrity model Cap
simulation model Cap
footprint 0603
footprint 0603M
footprint 0603L
footprint 0603_HV
footprint 0603S
pins: 1, 2

## GRM188R60J105KA01D
designator C?  ValueDisplayed: 1µF  (hidden comment: GRM188R60J105KA01D)
CAP, CERM, 1 µF, 6.3 V,+/- 10%, X5R, 0603; Manufacturer: MuRata; Polarized: N; CompType: Capacitor; Value: 1uF; U/M: EA; Cap_F: 0.000001; Tolerance_%: 10; VDC_V: 6.3; Value2: 6.3V; TaMin_C: -55; TaMax_C: 85; Cap_Case: 0603; SizeArea_mm2: 1.28; SizeAreaWB_mm2: 4.68; SizeX_mm: 1.6; SizeY_mm: 0.8; SizeZ_mm: 1; AEC Category: Q200; Green_Lifecycle: Active; Green_REACh: Passed
signal-integrity model Cap
simulation model Cap
footprint 0603
footprint 0603M
footprint 0603L
footprint 0603_HV
footprint 0603S
pins: 1, 2

## GRM188R60J106ME47D
designator C?  ValueDisplayed: 10µF  (hidden comment: GRM188R60J106ME47D)
CAP, CERM, 10 µF, 6.3 V,+/- 20%, X5R, 0603; Manufacturer: MuRata; Polarized: N; CompType: Capacitor; Value: 10uF; U/M: EA; Cap_F: 0.00001; Tolerance_%: 20; ESR_ohm: 0.009; Value1: 0.009 ohm; VDC_V: 6.3; Value2: 6.3V; IRMS_A: 2.74; TaMin_C: -55; TaMax_C: 125; Cap_Case: 0603; SizeArea_mm2: 1.28; SizeAreaWB_mm2: 4.68; SizeX_mm: 1.6; SizeY_mm: 0.8; SizeZ_mm: 1; AEC Category: Q200; Green_Lifecycle: Active; Green_REACh: Passed
signal-integrity model Cap
simulation model Cap
footprint 0603
footprint 0603M
footprint 0603L
footprint 0603_HV
footprint 0603S
pins: 1, 2

## GRM188R60J106ME84
designator C?  ValueDisplayed: 10µF  (hidden comment: GRM188R60J106ME84)
CAP, CERM, 10 µF, 6.3 V,+/- 20%, X5R, 0603; Manufacturer: MuRata; Polarized: N; CompType: Capacitor; Value: 10uF; U/M: EA; Cap_F: 0.00001; Tolerance_%: 20; VDC_V: 6.3; Value2: 6.3V; TaMin_C: -55; TaMax_C: 85; Cap_Case: 0603; SizeArea_mm2: 1.28; SizeAreaWB_mm2: 4.68; SizeX_mm: 1.6; SizeY_mm: 0.8; SizeZ_mm: 1; AEC Category: Q200; Green_Lifecycle: Active; Green_REACh: Passed
signal-integrity model Cap
simulation model Cap
footprint 0603
footprint 0603M
footprint 0603L
footprint 0603_HV
footprint 0603S
pins: 1, 2

## GRM188R60J225KE19D
designator C?  ValueDisplayed: 2.2µF  (hidden comment: GRM188R60J225KE19D)
CAP, CERM, 2.2 µF, 6.3 V,+/- 10%, X5R, 0603; Manufacturer: MuRata; Polarized: N; CompType: Capacitor; Value: 2.2uF; U/M: EA; Cap_F: 0.0000022; Tolerance_%: 10; VDC_V: 6.3; Value2: 6.3V; TaMin_C: -55; TaMax_C: 85; Cap_Case: 0603; SizeArea_mm2: 1.28; SizeAreaWB_mm2: 4.68; SizeX_mm: 1.6; SizeY_mm: 0.8; SizeZ_mm: 1; AEC Category: Q200; Green_Lifecycle: Active; Green_REACh: Passed
signal-integrity model Cap
simulation model Cap
footprint 0603
footprint 0603M
footprint 0603L
footprint 0603_HV
footprint 0603S
pins: 1, 2

## GRM188R60J226MEA0D
designator C?  ValueDisplayed: 22µF  (hidden comment: GRM188R60J226MEA0D)
CAP, CERM, 22 µF, 6.3 V,+/- 20%, X5R, 0603; Manufacturer: MuRata; Polarized: N; CompType: Capacitor; Value: 22uF; U/M: EA; Cap_F: 0.000022; Tolerance_%: 20; VDC_V: 6.3; Value2: 6.3V; TaMin_C: -55; TaMax_C: 85; Cap_Case: 0603; SizeArea_mm2: 1.28; SizeAreaWB_mm2: 4.68; SizeX_mm: 1.6; SizeY_mm: 0.8; SizeZ_mm: 1; AEC Category: Q200; Green_Lifecycle: Active; Green_REACh: Passed
signal-integrity model Cap
simulation model Cap
footprint 0603
footprint 0603M
footprint 0603L
footprint 0603_HV
footprint 0603S
pins: 1, 2

## GRM188R60J226MEA0J
designator C?  ValueDisplayed: 22µF  (hidden comment: GRM188R60J226MEA0J)
CAP, CERM, 22 µF, 6.3 V,+/- 20%, X5R, 0603; Manufacturer: MuRata; Polarized: N; CompType: Capacitor; Value: 22uF; U/M: EA; Cap_F: 0.000022; Tolerance_%: 20; VDC_V: 6.3; Value2: 6.3V; TaMin_C: -55; TaMax_C: 85; Cap_Case: 0603; SizeArea_mm2: 1.28; SizeAreaWB_mm2: 4.68; SizeX_mm: 1.6; SizeY_mm: 0.8; SizeZ_mm: 1; AEC Category: Q200; Green_Lifecycle: Active; Green_REACh: Passed
signal-integrity model Cap
simulation model Cap
footprint 0603
footprint 0603M
footprint 0603L
footprint 0603_HV
footprint 0603S
pins: 1, 2

## GRM188R60J334KA01D
designator C?  ValueDisplayed: 0.33µF  (hidden comment: GRM188R60J334KA01D)
CAP, CERM, 0.33 µF, 6.3 V,+/- 10%, X5R, 0603; Manufacturer: MuRata; Polarized: N; CompType: Capacitor; Value: 0.33uF; U/M: EA; Cap_F: 0.00000033; Tolerance_%: 10; VDC_V: 6.3; Value2: 6.3V; TaMin_C: -55; TaMax_C: 85; Cap_Case: 0603; SizeArea_mm2: 1.28; SizeAreaWB_mm2: 4.68; SizeX_mm: 1.6; SizeY_mm: 0.8; SizeZ_mm: 1; AEC Category: Q200
signal-integrity model Cap
simulation model Cap
footprint 0603
footprint 0603M
footprint 0603L
footprint 0603_HV
footprint 0603S
pins: 1, 2

## GRM188R60J394KA01D
designator C?  ValueDisplayed: 0.39µF  (hidden comment: GRM188R60J394KA01D)
CAP, CERM, 0.39 µF, 6.3 V,+/- 10%, X5R, 0603; Manufacturer: MuRata; Polarized: N; CompType: Capacitor; Value: 0.39uF; U/M: EA; Cap_F: 0.00000039; Tolerance_%: 10; VDC_V: 6.3; Value2: 6.3V; TaMin_C: -55; TaMax_C: 85; Cap_Case: 0603; SizeArea_mm2: 1.28; SizeAreaWB_mm2: 4.68; SizeX_mm: 1.6; SizeY_mm: 0.8; SizeZ_mm: 1; AEC Category: Q200
signal-integrity model Cap
simulation model Cap
footprint 0603
footprint 0603M
footprint 0603L
footprint 0603_HV
footprint 0603S
pins: 1, 2

## GRM188R60J474KA01D
designator C?  ValueDisplayed: 0.47µF  (hidden comment: GRM188R60J474KA01D)
CAP, CERM, 0.47 µF, 6.3 V,+/- 10%, X5R, 0603; Manufacturer: MuRata; Polarized: N; CompType: Capacitor; Value: 0.47uF; U/M: EA; Cap_F: 0.00000047; Tolerance_%: 10; VDC_V: 6.3; Value2: 6.3V; TaMin_C: -55; TaMax_C: 85; Cap_Case: 0603; SizeArea_mm2: 1.28; SizeAreaWB_mm2: 4.68; SizeX_mm: 1.6; SizeY_mm: 0.8; SizeZ_mm: 1; AEC Category: Q200
signal-integrity model Cap
simulation model Cap
footprint 0603
footprint 0603M
footprint 0603L
footprint 0603_HV
footprint 0603S
pins: 1, 2

## GRM188R60J475KE19D
designator C?  ValueDisplayed: 4.7µF  (hidden comment: GRM188R60J475KE19D)
CAP, CERM, 4.7 µF, 6.3 V,+/- 10%, X5R, 0603; Manufacturer: MuRata; Polarized: N; CompType: Capacitor; Value: 4.7uF; U/M: EA; Cap_F: 0.0000047; Tolerance_%: 10; ESR_ohm: 0.005; Value1: 0.005 ohm; VDC_V: 6.3; Value2: 6.3V; IRMS_A: 2; TaMin_C: -55; TaMax_C: 85; Cap_Case: 0603; SizeArea_mm2: 1.28; SizeAreaWB_mm2: 4.68; SizeX_mm: 1.6; SizeY_mm: 0.8; SizeZ_mm: 1; AEC Category: Q200; Green_Lifecycle: Active; Green_REACh: Passed
signal-integrity model Cap
simulation model Cap
footprint 0603
footprint 0603M
footprint 0603L
footprint 0603_HV
footprint 0603S
pins: 1, 2

## GRM188R60J475ME19D
designator C?  ValueDisplayed: 4.7µF  (hidden comment: GRM188R60J475ME19D)
CAP, CERM, 4.7 µF, 6.3 V,+/- 20%, X5R, 0603; Manufacturer: MuRata; Polarized: N; CompType: Capacitor; Value: 4.7uF; U/M: EA; Cap_F: 0.0000047; Tolerance_%: 20; ESR_ohm: 0.001; Value1: 0.001 ohm; VDC_V: 6.3; Value2: 6.3V; TaMin_C: -55; TaMax_C: 85; Cap_Case: 0603; SizeArea_mm2: 1.28; SizeAreaWB_mm2: 4.68; SizeX_mm: 1.6; SizeY_mm: 0.8; SizeZ_mm: 1; AEC Category: Q200; Green_Lifecycle: Active; Green_REACh: Passed
signal-integrity model Cap
simulation model Cap
footprint 0603
footprint 0603M
footprint 0603L
footprint 0603_HV
footprint 0603S
pins: 1, 2

## GRM188R60J476ME15D
designator C?  ValueDisplayed: 47µF  (hidden comment: GRM188R60J476ME15D)
CAP, CERM, 47 µF, 6.3 V,+/- 20%, X5R, 0603; Manufacturer: MuRata; Polarized: N; CompType: Capacitor; Value: 47uF; U/M: EA; Cap_F: 0.000047; Tolerance_%: 20; VDC_V: 6.3; Value2: 6.3V; TaMin_C: -55; TaMax_C: 85; Cap_Case: 0603; SizeArea_mm2: 1.28; SizeAreaWB_mm2: 4.68; SizeX_mm: 1.6; SizeY_mm: 0.8; SizeZ_mm: 1; AEC Category: Q200; Green_Lifecycle: Active; Green_REACh: Passed
signal-integrity model Cap
simulation model Cap
footprint 0603
footprint 0603M
footprint 0603L
footprint 0603_HV
footprint 0603S
pins: 1, 2

## GRM188R60J564KA01D
designator C?  ValueDisplayed: 0.56µF  (hidden comment: GRM188R60J564KA01D)
CAP, CERM, 0.56 µF, 6.3 V,+/- 10%, X5R, 0603; Manufacturer: MuRata; Polarized: N; CompType: Capacitor; Value: 0.56uF; U/M: EA; Cap_F: 0.00000056; Tolerance_%: 10; VDC_V: 6.3; Value2: 6.3V; TaMin_C: -55; TaMax_C: 85; Cap_Case: 0603; SizeArea_mm2: 1.28; SizeAreaWB_mm2: 4.68; SizeX_mm: 1.6; SizeY_mm: 0.8; SizeZ_mm: 1; AEC Category: Q200
signal-integrity model Cap
simulation model Cap
footprint 0603
footprint 0603M
footprint 0603L
footprint 0603_HV
footprint 0603S
pins: 1, 2

## GRM188R60J684KA01D
designator C?  ValueDisplayed: 0.68µF  (hidden comment: GRM188R60J684KA01D)
CAP, CERM, 0.68 µF, 6.3 V,+/- 10%, X5R, 0603; Manufacturer: MuRata; Polarized: N; CompType: Capacitor; Value: 0.68uF; U/M: EA; Cap_F: 0.00000068; Tolerance_%: 10; VDC_V: 6.3; Value2: 6.3V; TaMin_C: -55; TaMax_C: 85; Cap_Case: 0603; SizeArea_mm2: 1.28; SizeAreaWB_mm2: 4.68; SizeX_mm: 1.6; SizeY_mm: 0.8; SizeZ_mm: 1; AEC Category: Q200
signal-integrity model Cap
simulation model Cap
footprint 0603
footprint 0603M
footprint 0603L
footprint 0603_HV
footprint 0603S
pins: 1, 2

## GRM188R60J824KA01D
designator C?  ValueDisplayed: 0.82µF  (hidden comment: GRM188R60J824KA01D)
CAP, CERM, 0.82 µF, 6.3 V,+/- 10%, X5R, 0603; Manufacturer: MuRata; Polarized: N; CompType: Capacitor; Value: 0.82uF; U/M: EA; Cap_F: 0.00000082; Tolerance_%: 10; VDC_V: 6.3; Value2: 6.3V; TaMin_C: -55; TaMax_C: 85; Cap_Case: 0603; SizeArea_mm2: 1.28; SizeAreaWB_mm2: 4.68; SizeX_mm: 1.6; SizeY_mm: 0.8; SizeZ_mm: 1; AEC Category: Q200
signal-integrity model Cap
simulation model Cap
footprint 0603
footprint 0603M
footprint 0603L
footprint 0603_HV
footprint 0603S
pins: 1, 2

## GRM188R61A105KA61D
designator C?  ValueDisplayed: 1µF  (hidden comment: GRM188R61A105KA61D)
CAP, CERM, 1 µF, 10 V,+/- 10%, X5R, 0603; Manufacturer: MuRata; Polarized: N; CompType: Capacitor; Value: 1uF; U/M: EA; Cap_F: 0.000001; Tolerance_%: 10; Value2: 10V; TaMin_C: -55; TaMax_C: 85; Cap_Case: 0603; SizeArea_mm2: 1.28; SizeAreaWB_mm2: 4.68; SizeX_mm: 1.6; SizeY_mm: 0.8; SizeZ_mm: 1; AEC Category: Q200; Green_Lifecycle: Active; Green_REACh: Passed
signal-integrity model Cap
simulation model Cap
footprint 0603
footprint 0603M
footprint 0603L
footprint 0603_HV
footprint 0603S
pins: 1, 2

## GRM188R61A106MAALD
designator C?  ValueDisplayed: 10µF  (hidden comment: GRM188R61A106MAALD)
CAP, CERM, 10 µF, 10 V,+/- 20%, X5R, 0603; Manufacturer: MuRata; Polarized: N; CompType: Capacitor; Value: 10uF; U/M: EA; Cap_F: 0.00001; Tolerance_%: 20; VDC_V: 10; Value2: 10V; TaMin_C: -55; TaMax_C: 85; Cap_Case: 0603; SizeArea_mm2: 1.28; SizeAreaWB_mm2: 4.68; SizeX_mm: 1.6; SizeY_mm: 0.8; SizeZ_mm: 1; AEC Category: Q200
signal-integrity model Cap
simulation model Cap
footprint 0603
footprint 0603M
footprint 0603L
footprint 0603_HV
footprint 0603S
pins: 1, 2

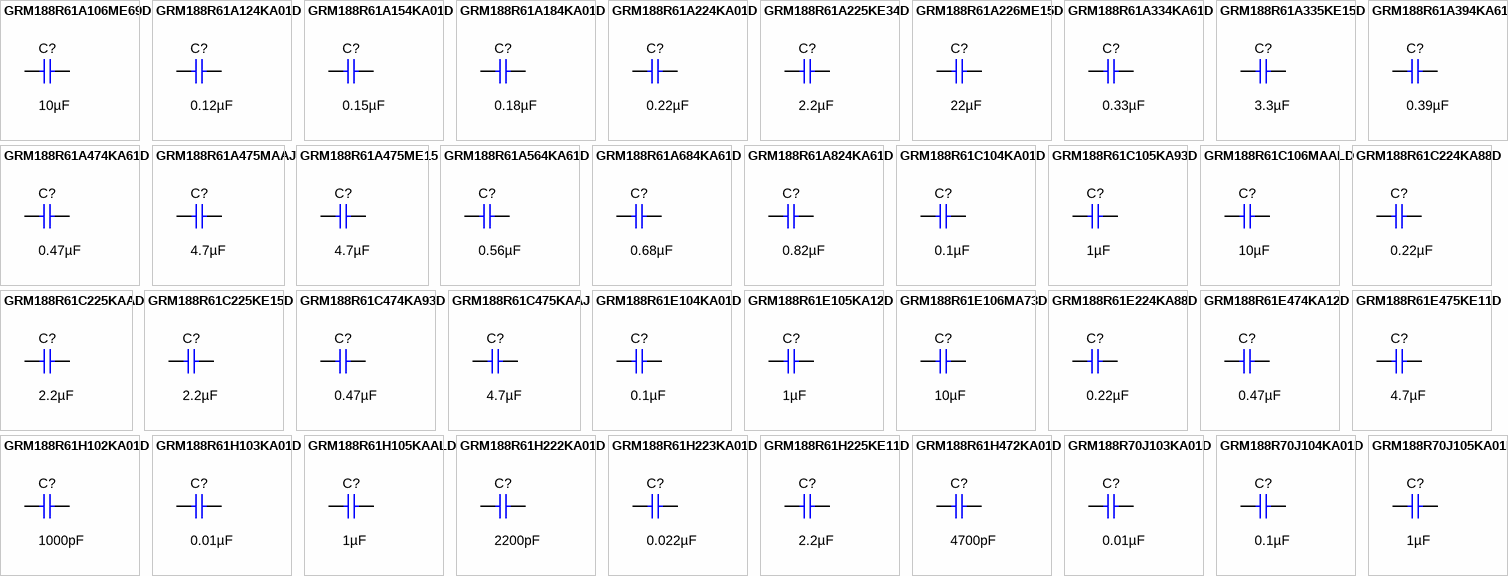
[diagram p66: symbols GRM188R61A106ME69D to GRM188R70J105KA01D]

## GRM188R61A106ME69D
designator C?  ValueDisplayed: 10µF  (hidden comment: GRM188R61A106ME69D)
CAP, CERM, 10 µF, 10 V,+/- 20%, X5R, 0603; Manufacturer: MuRata; Polarized: N; CompType: Capacitor; Value: 10uF; U/M: EA; Cap_F: 0.00001; Tolerance_%: 20; VDC_V: 10; Value2: 10V; TaMin_C: -55; TaMax_C: 85; Cap_Case: 0603; SizeArea_mm2: 1.28; SizeAreaWB_mm2: 4.68; SizeX_mm: 1.6; SizeY_mm: 0.8; SizeZ_mm: 1; AEC Category: Q200; Green_Lifecycle: Active; Green_REACh: Passed
signal-integrity model Cap
simulation model Cap
footprint 0603
footprint 0603M
footprint 0603L
footprint 0603_HV
footprint 0603S
pins: 1, 2

## GRM188R61A124KA01D
designator C?  ValueDisplayed: 0.12µF  (hidden comment: GRM188R61A124KA01D)
CAP, CERM, 0.12 µF, 10 V,+/- 10%, X5R, 0603; Manufacturer: MuRata; Polarized: N; CompType: Capacitor; Value: 0.12uF; U/M: EA; Cap_F: 0.00000012; Tolerance_%: 10; Value2: 10V; TaMin_C: -55; TaMax_C: 85; Cap_Case: 0603; SizeArea_mm2: 1.28; SizeAreaWB_mm2: 4.68; SizeX_mm: 1.6; SizeY_mm: 0.8; SizeZ_mm: 1; AEC Category: Q200
signal-integrity model Cap
simulation model Cap
footprint 0603
footprint 0603M
footprint 0603L
footprint 0603_HV
footprint 0603S
pins: 1, 2

## GRM188R61A154KA01D
designator C?  ValueDisplayed: 0.15µF  (hidden comment: GRM188R61A154KA01D)
CAP, CERM, 0.15 µF, 10 V,+/- 10%, X5R, 0603; Manufacturer: MuRata; Polarized: N; CompType: Capacitor; Value: 0.15uF; U/M: EA; Cap_F: 0.00000015; Tolerance_%: 10; Value2: 10V; TaMin_C: -55; TaMax_C: 85; Cap_Case: 0603; SizeArea_mm2: 1.28; SizeAreaWB_mm2: 4.68; SizeX_mm: 1.6; SizeY_mm: 0.8; SizeZ_mm: 1; AEC Category: Q200
signal-integrity model Cap
simulation model Cap
footprint 0603
footprint 0603M
footprint 0603L
footprint 0603_HV
footprint 0603S
pins: 1, 2

## GRM188R61A184KA01D
designator C?  ValueDisplayed: 0.18µF  (hidden comment: GRM188R61A184KA01D)
CAP, CERM, 0.18 µF, 10 V,+/- 10%, X5R, 0603; Manufacturer: MuRata; Polarized: N; CompType: Capacitor; Value: 0.18uF; U/M: EA; Cap_F: 0.00000018; Tolerance_%: 10; Value2: 10V; TaMin_C: -55; TaMax_C: 85; Cap_Case: 0603; SizeArea_mm2: 1.28; SizeAreaWB_mm2: 4.68; SizeX_mm: 1.6; SizeY_mm: 0.8; SizeZ_mm: 1; AEC Category: Q200
signal-integrity model Cap
simulation model Cap
footprint 0603
footprint 0603M
footprint 0603L
footprint 0603_HV
footprint 0603S
pins: 1, 2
